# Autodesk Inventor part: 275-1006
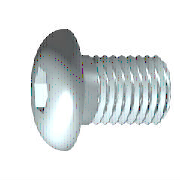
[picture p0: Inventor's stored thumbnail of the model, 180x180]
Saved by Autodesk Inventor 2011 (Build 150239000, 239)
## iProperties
Created: 2010-02
Part Number: 275-1006
Material: Steel, Mild
Description: Hexagon Socket Button Head Cap Screw
Document SubType Name: Modeling
Standard: ANSI B18.3
Designer: Autodesk Inc.
Standard Revision: 2003
Standards Organization: ANSI
Language: en-US
Size Designation: 8 - 32 x 3/4
Categories: <MemberInstance><Categories><Category DisplayName="Fasteners" InternalName="e4da775c-781d-43d5-af7c-5136215cf5a6" Mnemonic="FSTN"><Category DisplayName="Bolts"
Density: 1 g/cm^3
Catalog Web Link: http://www.vexrobotics.com/screws-8-32.html
Vendor: Innovation First, Inc.
Company: Autodesk Inc.
IsCustomPart: 0
Author: Autodesk Inc.
Title: VEX Robotics Kit of Parts
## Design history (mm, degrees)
revolve "Body" stored, may be unused: angle "d10" = 90 deg
sketch "Sketch2"
  geometry: L1 (0, -5.547)-(0, 5.547) reference; L2 (-5.547, 0)-(5.547, 0) reference; L3 (1.378, 0)-(0.689, -1.194); L4 (0.689, -1.194)-(-0.689, -1.194); L5 (-0.689, -1.194)-(-1.378, 0); L6 (-1.378, 0)-(-0.689, 1.194); L7 (-0.689, 1.194)-(0.689, 1.194); L8 (0.689, 1.194)-(1.378, 0); 2 further points
  constraints: 12 end point, 1 coincident, 1 horizontal alignment, 1 point on line, 12 other
extrude "Slot" join sketch "Sketch2" stored distance "d11" = 10; taper "d12" = 0 deg
workplane "Work Plane1"
fillet "Fillet2" dims "d30" = 0.1 (= R)
body "Solid1"
fillet "Fillet1" dims "d17" = 1.9558 (= RR)
feature "Thread" dims "d13" = 17.45976 (= GEL), "d14" = 0
chamfer "Chamfer1" distance "d15" = 0.48692 (= -0.5 x SPD + 0.5 x GD); stored, may be unused: second distance "d16" = 0.48692 (= GUL), angle "d27" = 45 deg
sketch "Sketch1"
  geometry: L1 (-0.093, 0)-(19.05, 0); L2 (19.05, 0)-(19.05, 2.083); L3 (19.05, 2.083)-(1.59, 2.083); L4 (1.59, 2.083)-(0, 2.083); L5 (0, 2.083)-(0, 2.083); L6 (0, 2.083)-(0, 3.962); L7 (0, 3.962)-(-2.21, 3.962); L8 (-2.21, 3.962)-(-2.21, 1.378); L9 (-2.21, 1.378)-(-0.889, 1.378); L10 (-0.889, 1.378)-(-0.093, 0); L11 (-6.462, 0)-(23.302, 0) reference; L12 (0, -0.792)-(0, 4.755) reference; L13 (1.59, 2.083)-(0, 2.083)
  constraints: 22 end point, 6 parallel, 2 collinear, 2 perpendicular, 1 horizontal, 1 point on line
  dimensions: "d1" = 17.45976 distance from line of L3.end L2 (= GEL); "d2" = 1.59014 distance of L4.end L3.end (computed from GAL); "d3" = 2.2098 distance between parallel lines of L8 L6 (= KOH); "d4" = 1.3208 distance of L8.end L9.end (= INTI); "d5" = 60 deg angle of L10 L1; "d6" = 4.1656 diameter of L3 L1 (= GD); "d7" = 4.1656 diameter of L5 L1 (= BDM); "d8" = 2.75696 diameter of L9 L1 (= 1.1547 x SW); "d9" = 7.9248 diameter of L7 L1 (= KOD); "d26" = 19.05 distance between parallel lines of L12 L2 (= NLG)
other parameters: "GD" = 4.1656 (= NND) [user parameter; used in 2 equation terms], "NLG" = 19.05 [user parameter; used in 1 equation term], "GEL" = 17.45976 [user parameter; used in 2 equation terms], "KOD" = 7.9248 [user parameter; used in 1 equation term], "KOH" = 2.2098 [user parameter; used in 1 equation term], "INTI" = 1.3208 [user parameter; used in 1 equation term], "GAL" = 1.59004 [user parameter; used in 1 equation term], "GUL" = 0.48692 [user parameter; used in 1 equation term], "BDM" = 4.1656 (= NND) [user parameter; used in 1 equation term], "SW" = 2.3876 [user parameter; used in 1 equation term], "RR" = 1.9558 [user parameter; used in 1 equation term], "SPD" = 3.19176 [user parameter; used in 2 equation terms], "d19" = 0, "d28" = 0, "d29" = 0, "R" = 0.1 [user parameter; used in 1 equation term], "TOA" = 30 deg [user parameter], "GD1" = 3.19176 (= SPD) [user parameter], "THREADDIA" = 4.1656 [user parameter], "PTC" = 0.79375 (computed from TPU) [user parameter], "KOH1" = 0.381 [user parameter], "NND" = 4.1656 [user parameter; used in 2 equation terms], "E0" = 2.75768 [user parameter]
